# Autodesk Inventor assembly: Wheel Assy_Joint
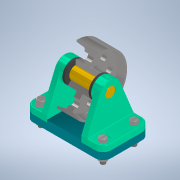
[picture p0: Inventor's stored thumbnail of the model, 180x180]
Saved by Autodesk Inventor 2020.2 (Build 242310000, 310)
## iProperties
Created: 2020-01
Part Number: Wheel Assy_Joint
Document SubType Name: Assembly
Designer: thira
Author: thira
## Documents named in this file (11)
- C:\Users\thira\OneDrive\เดสก์ท็อป\INV-01 Intro to Modeling_2020\Wheel Assem Final V1\Wheel Assy_Joint.iam
- C:\Users\thira\OneDrive\เดสก์ท็อป\INV-01 Intro to Modeling_2020\Wheel Assem Final V1\Plate V1.ipt
- C:\Users\thira\OneDrive\เดสก์ท็อป\INV-01 Intro to Modeling_2020\Wheel Assem Final V1\Shaft V1.ipt
- C:\Users\thira\OneDrive\เดสก์ท็อป\INV-01 Intro to Modeling_2020\Wheel Assem Final V1\Support Wheel V1.ipt
- C:\Users\thira\OneDrive\เดสก์ท็อป\INV-01 Intro to Modeling_2020\Wheel Assem Final V1\Wheel V1.ipt
- C:\Users\thira\OneDrive\เดสก์ท็อป\INV-01 Intro to Modeling_2020\Wheel Assem Final V1\Seal.ipt
- C:\Users\thira\OneDrive\เอกสาร\Inventor\Content Center Files\R2020\en-US\ISO 1207(2)\ISO 1207 - M8 x 35.ipt
- C:\Users\thira\OneDrive\เอกสาร\Inventor\Content Center Files\R2020\en-US\ISO 7089\ISO 7089 - 10 - 140 HV(1).ipt
- C:\Users\thira\OneDrive\เอกสาร\Inventor\Content Center Files\R2020\en-US\ISO 4032(2)\ISO 4032 - M8 - ISO.ipt
- C:\Users\thira\OneDrive\เดสก์ท็อป\INV-01 Intro to Modeling_2020\Wheel Assem Final V1\Wheel Assy_Joint\Design Accelerator\Bolted Connection1.iam
- C:\Users\thira\OneDrive\เดสก์ท็อป\INV-01 Intro to Modeling_2020\Wheel Assem Final V1\Wheel Assy_Joint\Design Accelerator\Bolted Connection2.iam
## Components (17 placed, 9 different names)
1. Plate V1:1 — Rigid:1, Mate:1, Flush:1, Flush:2, Angle:1
2. Shaft V1:1 — Cylindrical:1, Planar:1, Cylindrical:2, Planar:2, Mate:2, Rotational:1
3. Support Wheel V1:1 — Rigid:1, Cylindrical:1, Planar:1, Flush:3, Flush:4, Mate:12, Mate:13, Mate:14, Mate:15
4. Wheel V1:1 — Cylindrical:2, Planar:2, Angle:1, Rotational:1
5. Support Wheel V1:2 — Mate:1, Flush:1, Flush:2, Mate:3
6. Seal:1 — Flush:3, Flush:4
7. Seal:2 — Mate:2, Mate:3
8. ISO 1207 M8 x 35:1
9. ISO 1207 M8 x 35:2
10. ISO 7089 10:1 — Mate:11
11. ISO 7089 10:2
12. ISO 7089 10:3 — Mate:9
13. ISO 7089 10:4
14. ISO 4032 M8:1 — Mate:9
15. ISO 4032 M8:2 — Mate:11
16. Bolted Connection:1 [sub-assembly] — Mate:12, Mate:13
17. Bolted Connection:2 [sub-assembly] — Mate:14, Mate:15
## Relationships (20: Mate 9, Flush 4, CylindricalJoint 2, PlanarJoint 2, WeldJoint 1, Angle 1, RevoluteJoint 1)
- Rigid:1 [WeldJoint]: Plate V1:1 ↔ Support Wheel V1:1
- Mate:1: Plate V1:1 ↔ Support Wheel V1:2
- Flush:1: Plate V1:1 ↔ Support Wheel V1:2
- Flush:2: Plate V1:1 ↔ Support Wheel V1:2
- Cylindrical:1: Shaft V1:1 ↔ Support Wheel V1:1
- Planar:1: Shaft V1:1 ↔ Support Wheel V1:1
- Cylindrical:2: Shaft V1:1 ↔ Wheel V1:1
- Planar:2: Shaft V1:1 ↔ Wheel V1:1
- Flush:3: Support Wheel V1:1 ↔ Seal:1
- Flush:4: Support Wheel V1:1 ↔ Seal:1
- Mate:2: Shaft V1:1 ↔ Seal:2
- Mate:3: Support Wheel V1:2 ↔ Seal:2
- Angle:1: Plate V1:1 ↔ Wheel V1:1
- Rotational:1 [RevoluteJoint]: Shaft V1:1 ↔ Wheel V1:1
- Mate:9: ISO 7089 10:3 ↔ ISO 4032 M8:1
- Mate:11: ISO 7089 10:1 ↔ ISO 4032 M8:2
- Mate:12: Support Wheel V1:1 ↔ Bolted Connection:1
- Mate:13: Support Wheel V1:1 ↔ Bolted Connection:1
- Mate:14: Support Wheel V1:1 ↔ Bolted Connection:2
- Mate:15: Support Wheel V1:1 ↔ Bolted Connection:2
